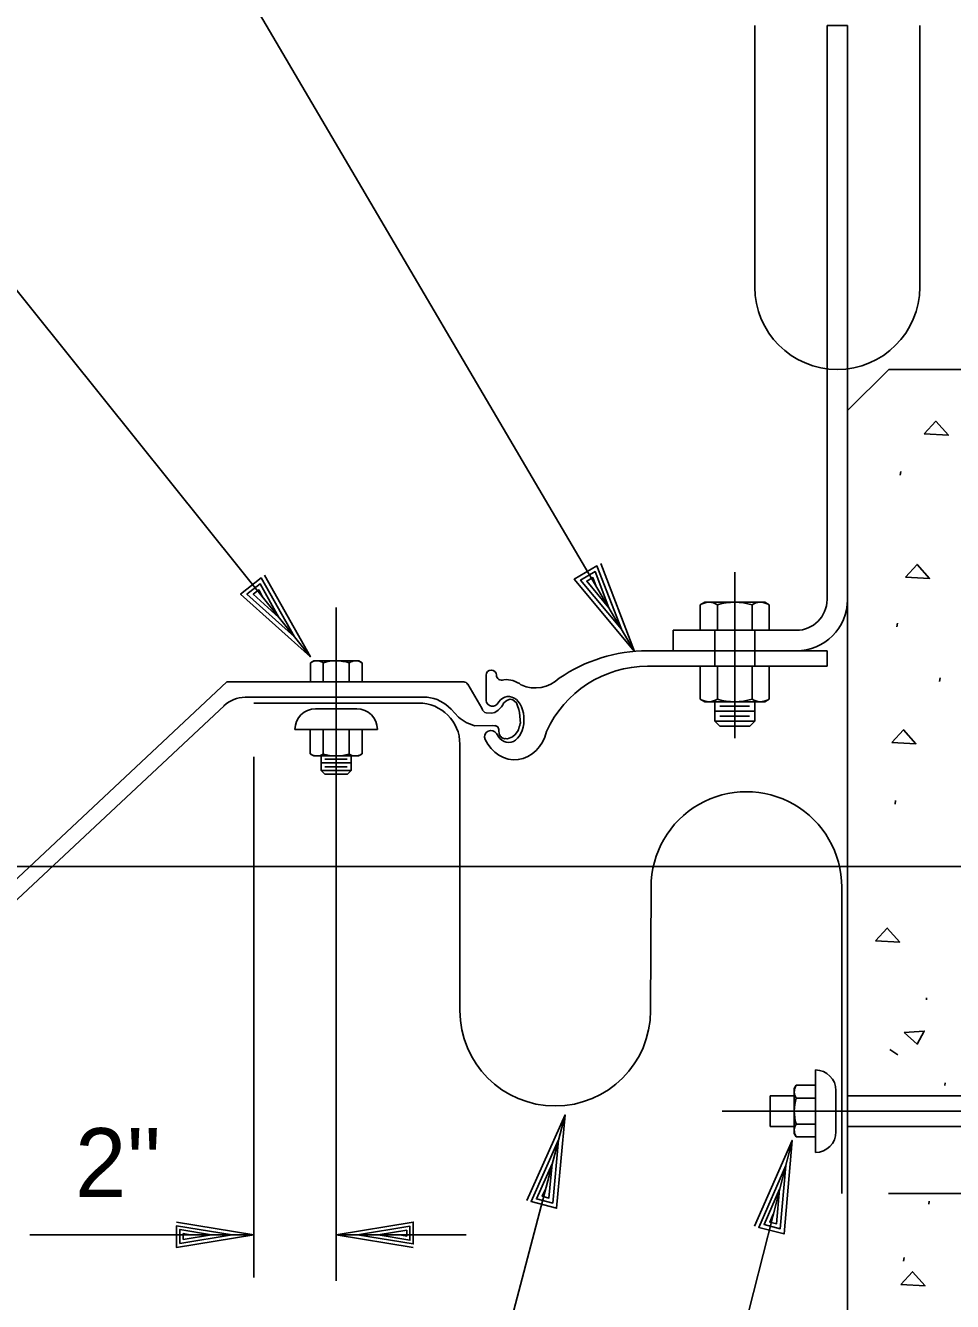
# Model space of a CAD drawing. Extents: x 22369.6 to 22428.3, y 22369.6 to 22415.
# Drawn here: x 22402.55 to 22405.041, y 22382.294 to 22385.725 of the extents above; entities that cross this region are included whole.
import ezdxf

# ---------------------------------------------------------------- set-up
doc = ezdxf.new("R2010")
doc.units = 0
for name, color, linetype in [('Level 1', 7, 'Continuous'), ('Level 10', 7, 'Continuous'), ('Level 2', 7, 'Continuous'), ('Level 3', 7, 'Continuous'), ('Level 4', 7, 'Continuous'), ('Level 7', 7, 'Continuous'), ('Level 8', 7, 'Continuous')]:
    doc.layers.add(name, color=color, linetype=linetype)

msp = doc.modelspace()

# ---------------------------------------------------------------- linework, layer by layer
at = {"layer": 'Level 1'}
for p, q in [((22404.1866, 22384.0421), (22402.6561, 22386.6455)), ((22402.4393, 22385.1206), (22403.3156, 22384.0274)), ((22404.456, 22384.2551), (22404.456, 22384.0022)), ((22403.3847, 22384.1599), (22403.3847, 22382.3487)), ((22404.3754, 22384.1741), (22404.3629, 22384.1669)), ((22404.3629, 22384.0987), (22404.3629, 22384.1669)), ((22404.3754, 22384.1741), (22404.5365, 22384.1741)), ((22404.4094, 22384.167), (22404.4094, 22384.0987)), ((22404.5026, 22384.167), (22404.5026, 22384.0987)), ((22404.5365, 22384.1741), (22404.549, 22384.1669)), ((22404.549, 22384.0987), (22404.549, 22384.1669)), ((22403.2723, 22384.0814), (22403.2723, 22384.0814)), ((22404.1515, 22384.1019), (22404.1515, 22384.1019)), ((22404.4021, 22384.0022), (22404.4021, 22384.0987)), ((22404.5099, 22384.0022), (22404.5099, 22384.0987)), ((22403.3249, 22384.0167), (22403.3155, 22384.0112)), ((22403.3155, 22383.9602), (22403.3155, 22384.0112)), ((22403.3156, 22384.0274), (22403.3156, 22384.0274)), ((22403.3249, 22384.0167), (22403.4454, 22384.0167)), ((22403.3502, 22384.0114), (22403.3502, 22383.9602)), ((22403.42, 22384.0114), (22403.42, 22383.9602)), ((22403.4454, 22384.0167), (22403.4548, 22384.0112)), ((22403.4548, 22383.9602), (22403.4548, 22384.0112)), ((22404.1866, 22384.0421), (22404.1866, 22384.0421)), ((22404.3629, 22384.0022), (22404.3629, 22383.9139)), ((22404.4094, 22383.9137), (22404.4094, 22384.0022)), ((22404.456, 22384.0022), (22404.456, 22384.0022)), ((22404.456, 22384.0022), (22404.456, 22383.809)), ((22404.5026, 22383.9137), (22404.5026, 22384.0022)), ((22404.549, 22384.0022), (22404.549, 22383.9139)), ((22404.3754, 22383.9066), (22404.3629, 22383.9139)), ((22404.5365, 22383.9066), (22404.549, 22383.9139)), ((22403.3293, 22383.8876), (22403.4402, 22383.8876)), ((22404.3754, 22383.9066), (22404.5365, 22383.9066)), ((22404.4021, 22383.8546), (22404.4021, 22383.9066)), ((22404.4021, 22383.8815), (22404.5099, 22383.8815)), ((22404.4157, 22383.8949), (22404.4958, 22383.8949)), ((22404.5099, 22383.8546), (22404.5099, 22383.9066)), ((22404.4021, 22383.8546), (22404.5099, 22383.8546)), ((22404.4021, 22383.8546), (22404.4156, 22383.8411)), ((22404.4156, 22383.8411), (22404.4964, 22383.8411)), ((22404.4157, 22383.868), (22404.4958, 22383.868)), ((22404.5099, 22383.8546), (22404.4964, 22383.8411)), ((22403.2739, 22383.8322), (22403.4956, 22383.8322)), ((22403.3151, 22383.8322), (22403.3151, 22383.7661)), ((22403.3499, 22383.7659), (22403.3499, 22383.8322)), ((22403.4196, 22383.7659), (22403.4196, 22383.8322)), ((22403.4543, 22383.8322), (22403.4543, 22383.7661)), ((22403.1631, 22383.7582), (22403.1631, 22382.3577)), ((22403.3245, 22383.7607), (22403.3151, 22383.7661)), ((22403.3245, 22383.7607), (22403.445, 22383.7607)), ((22403.3444, 22383.7217), (22403.3444, 22383.7607)), ((22403.3444, 22383.7419), (22403.4251, 22383.7419)), ((22403.3546, 22383.7519), (22403.4146, 22383.7519)), ((22403.4251, 22383.7217), (22403.4251, 22383.7607)), ((22403.445, 22383.7607), (22403.4543, 22383.7661)), ((22403.3444, 22383.7217), (22403.4251, 22383.7217)), ((22403.3444, 22383.7217), (22403.3545, 22383.7116)), ((22403.3545, 22383.7116), (22403.415, 22383.7116)), ((22403.3546, 22383.7318), (22403.4146, 22383.7318)), ((22403.4251, 22383.7217), (22403.415, 22383.7116)), ((22404.8872, 22383.6312), (22404.8886, 22383.6407)), ((22398.3749, 22383.4637), (22405.4638, 22383.4637)), ((22404.6728, 22382.6945), (22404.6728, 22382.9162)), ((22404.6161, 22382.8469), (22404.5514, 22382.8469)), ((22404.5514, 22382.7638), (22404.5514, 22382.8469)), ((22404.6161, 22382.866), (22404.6215, 22382.8754)), ((22404.6161, 22382.7455), (22404.6161, 22382.866)), ((22404.6725, 22382.8754), (22404.6215, 22382.8754)), ((22404.7282, 22382.7499), (22404.7282, 22382.8608)), ((22405.2026, 22382.8469), (22404.7592, 22382.8469)), ((22404.6214, 22382.8406), (22404.6725, 22382.8406)), ((22404.0001, 22382.7954), (22403.3267, 22380.2256)), ((22404.0001, 22382.7954), (22404.0001, 22382.7954)), ((22407.3997, 22382.8054), (22404.4222, 22382.8054)), ((22404.6161, 22382.7638), (22404.5514, 22382.7638)), ((22404.6161, 22382.7455), (22404.6215, 22382.7361)), ((22404.6214, 22382.7709), (22404.6725, 22382.7709)), ((22405.2026, 22382.7638), (22404.7592, 22382.7638)), ((22403.9826, 22382.7285), (22403.9826, 22382.7285)), ((22404.6102, 22382.7267), (22404.2046, 22381.1322)), ((22404.6102, 22382.7267), (22404.6102, 22382.7267)), ((22404.6725, 22382.7361), (22404.6215, 22382.7361)), ((22404.5931, 22382.6597), (22404.5931, 22382.6597)), ((22406.7358, 22382.5837), (22404.8694, 22382.5837)), ((22403.1631, 22382.4729), (22402.561, 22382.4729)), ((22403.1054, 22382.4729), (22403.1054, 22382.4729)), ((22403.1631, 22382.4729), (22403.1631, 22382.4729)), ((22403.7343, 22382.4729), (22403.3847, 22382.4729)), ((22403.3847, 22382.4729), (22403.3847, 22382.4729)), ((22403.4424, 22382.4729), (22403.4424, 22382.4729))]:
    msp.add_line(p, q, dxfattribs=at)
for points in [[(22404.0959, 22384.278), (22404.1866, 22384.0421), (22404.0246, 22384.2361), (22404.0856, 22384.2719), (22404.1515, 22384.1019), (22404.0415, 22384.2336), (22404.0806, 22384.2566), (22404.1177, 22384.1593), (22404.0584, 22384.2312), (22404.0745, 22384.2407), (22404.0826, 22384.2191)], [(22403.1922, 22384.2473), (22403.3156, 22384.0274), (22403.1279, 22384.1957), (22403.1829, 22384.2398), (22403.2723, 22384.0814), (22403.1449, 22384.1957), (22403.1802, 22384.224), (22403.2307, 22384.1333), (22403.1619, 22384.1957), (22403.1765, 22384.2074), (22403.1875, 22384.1872)], [(22403.8972, 22382.5653), (22404.0001, 22382.7954), (22403.977, 22382.5444), (22403.9088, 22382.5623), (22403.9826, 22382.7285), (22403.9668, 22382.5581), (22403.9231, 22382.5695), (22403.9657, 22382.6642), (22403.9566, 22382.5717), (22403.9386, 22382.5764), (22403.9482, 22382.5973)], [(22404.5089, 22382.4959), (22404.6102, 22382.7267), (22404.5888, 22382.4755), (22404.5205, 22382.4929), (22404.5931, 22382.6597), (22404.5786, 22382.4891), (22404.5347, 22382.5003), (22404.5767, 22382.5953), (22404.5683, 22382.5027), (22404.5502, 22382.5073), (22404.5597, 22382.5282)], [(22402.9558, 22382.5072), (22403.1631, 22382.4729), (22402.9558, 22382.4385), (22402.9558, 22382.4972), (22403.1054, 22382.4729), (22402.9647, 22382.4496), (22402.9647, 22382.4873), (22403.05, 22382.4729), (22402.9735, 22382.4607), (22402.9735, 22382.4762), (22402.9924, 22382.4729)], [(22403.592, 22382.4385), (22403.3847, 22382.4729), (22403.592, 22382.5072), (22403.592, 22382.4485), (22403.4424, 22382.4729), (22403.5831, 22382.4961), (22403.5831, 22382.4584), (22403.4978, 22382.4729), (22403.5743, 22382.4851), (22403.5743, 22382.4695), (22403.5554, 22382.4729)]]:
    msp.add_lwpolyline(points, dxfattribs=at)
for centre, radius, start, end in [((22404.3865, 22384.1338), 0.0404, 55.489, 120.2876), ((22404.4554, 22384.0125), 0.1616, 73.0184, 106.4966), ((22404.5255, 22384.1338), 0.0404, 59.7124, 124.511), ((22403.3331, 22383.9865), 0.0302, 55.489, 120.2876), ((22403.3847, 22383.8957), 0.1209, 73.0184, 106.4966), ((22403.4371, 22383.9865), 0.0302, 59.7124, 124.511), ((22404.3865, 22383.947), 0.0404, 239.7124, 304.511), ((22404.4554, 22384.0682), 0.1616, 253.5034, 286.9816), ((22404.5255, 22383.947), 0.0404, 235.489, 300.2876), ((22403.3293, 22383.8322), 0.0554, 90, 180), ((22403.4402, 22383.8322), 0.0554, 0, 90), ((22403.3328, 22383.7909), 0.0302, 239.7124, 304.511), ((22403.3843, 22383.8816), 0.1209, 253.5034, 286.9816), ((22403.4367, 22383.7909), 0.0302, 235.489, 300.2876), ((22404.6728, 22382.8608), 0.0554, 0, 90), ((22404.6463, 22382.8577), 0.0302, 149.7124, 214.511), ((22404.737, 22382.8053), 0.1209, 163.0184, 196.4966), ((22404.6463, 22382.7538), 0.0302, 145.489, 210.2876), ((22404.6728, 22382.7499), 0.0554, 270, 0)]:
    msp.add_arc(centre, radius, start, end, dxfattribs=at)
at = {"layer": 'Level 10'}
for p, q in [((22404.51, 22385.022), (22404.51, 22385.7253)), ((22404.9533, 22385.022), (22404.9533, 22385.7253))]:
    msp.add_line(p, q, dxfattribs=at)
msp.add_arc((22404.7317, 22385.022), 0.2217, 180, 0, dxfattribs=at)
at = {"layer": 'Level 2'}
for p, q in [((22404.7041, 22384.1814), (22404.7041, 22385.7253)), ((22404.7592, 22385.7253), (22404.7041, 22385.7253)), ((22404.7592, 22384.1814), (22404.7592, 22385.7253)), ((22404.6214, 22384.0987), (22404.2905, 22384.0987)), ((22404.2905, 22384.0435), (22404.2905, 22384.0987)), ((22404.7041, 22384.0435), (22404.2216, 22384.0435)), ((22404.7041, 22384.0435), (22404.7041, 22384.0022)), ((22403.7879, 22383.9082), (22403.7879, 22383.9778)), ((22403.8155, 22383.9783), (22403.8155, 22383.9778)), ((22404.7041, 22384.0022), (22404.2216, 22384.0022)), ((22402.0993, 22383.0308), (22403.0913, 22383.96)), ((22403.0913, 22383.96), (22403.728, 22383.96)), ((22403.7382, 22383.9541), (22403.7763, 22383.8895)), ((22403.1403, 22383.9186), (22403.6291, 22383.9186)), ((22402.0922, 22382.9675), (22403.0842, 22383.8966)), ((22403.6934, 22383.8865), (22403.7134, 22383.865)), ((22403.7576, 22383.8422), (22403.8041, 22383.8424))]:
    msp.add_line(p, q, dxfattribs=at)
msp.add_lwpolyline([(22403.7763, 22383.8895), (22403.7781, 22383.8846), (22403.7776, 22383.8846), (22403.7845, 22383.8778), (22403.788, 22383.8768), (22403.8034, 22383.8763), (22403.811, 22383.8776), (22403.8203, 22383.8836), (22403.8295, 22383.8932), (22403.8325, 22383.8986), (22403.8338, 22383.8998), (22403.8347, 22383.9026), (22403.8408, 22383.9084), (22403.8452, 22383.9112), (22403.8524, 22383.9137), (22403.8595, 22383.9115), (22403.8694, 22383.9041), (22403.8724, 22383.8953), (22403.8757, 22383.8857), (22403.8777, 22383.8781), (22403.88, 22383.8483), (22403.8795, 22383.8487), (22403.8787, 22383.8429), (22403.877, 22383.8387), (22403.8747, 22383.8308), (22403.8719, 22383.8262), (22403.8663, 22383.8184), (22403.8586, 22383.8126), (22403.8545, 22383.8101), (22403.8452, 22383.807), (22403.8441, 22383.8073), (22403.8436, 22383.8066), (22403.8398, 22383.8073), (22403.8375, 22383.8071), (22403.831, 22383.8096), (22403.8289, 22383.8101), (22403.8289, 22383.8109), (22403.8256, 22383.8143), (22403.8231, 22383.8205), (22403.8224, 22383.8296), (22403.8223, 22383.8318), (22403.8191, 22383.8389), (22403.812, 22383.8426), (22403.8117, 22383.8417), (22403.8117, 22383.8422), (22403.8041, 22383.8424)], dxfattribs=at)
for centre, radius, start, end in [((22404.6214, 22384.1814), 0.0827, 270, 0), ((22404.6214, 22384.1814), 0.1378, 270, 0), ((22404.2216, 22383.6248), 0.4187, 90, 124.5362), ((22403.8017, 22383.9778), 0.0138, 0, 180), ((22403.8293, 22383.9783), 0.0138, 180.0038, 294.2261), ((22404.2216, 22383.7052), 0.297, 90, 155.9098), ((22403.7268, 22383.9462), 0.0138, 34.4776, 84.9264), ((22403.8419, 22383.9028), 0.0633, 50.4241, 96.2781), ((22403.9195, 22384.0366), 0.0928, 246.293, 314.0783), ((22403.1403, 22383.8359), 0.0827, 90, 134.0411), ((22403.6189, 22383.8175), 0.1017, 42.8324, 84.2307), ((22403.8048, 22383.9117), 0.0172, 168.5103, 315.7394), ((22403.1403, 22383.8359), 0.0827, 132.7844, 133.4737), ((22403.7875, 22383.954), 0.1157, 230.268, 255.0673), ((22403.8007, 22383.8123), 0.0171, 30.0864, 204.1441)]:
    msp.add_arc(centre, radius, start, end, dxfattribs=at)
for centre, major_axis, ratio, start_param, end_param in [((22403.8482, 22383.8588), (0, -0.062), 0.666679, 5.371054, 10.276478), ((22403.8641, 22383.854), (0, -0.1034), 0.866676, 5.202938, 7.584426)]:
    msp.add_ellipse(centre, major_axis=major_axis, ratio=ratio, start_param=start_param, end_param=end_param, dxfattribs=at)
at = {"layer": 'Level 3'}
for p, q in [((22403.1631, 22383.9031), (22403.6064, 22383.9031)), ((22403.7172, 22383.7923), (22403.7172, 22383.0758)), ((22404.2298, 22383.0758), (22404.2311, 22383.4083)), ((22404.7437, 22383.4083), (22404.7437, 22382.5837))]:
    msp.add_line(p, q, dxfattribs=at)
for centre, radius, start, end in [((22403.6064, 22383.7923), 0.1108, 0, 90), ((22404.4874, 22383.4083), 0.2563, 359.9969, 180), ((22403.9735, 22383.0758), 0.2563, 180, 0)]:
    msp.add_arc(centre, radius, start, end, dxfattribs=at)
at = {"layer": 'Level 7'}
for p, q in [((22404.8701, 22384.8004), (22404.7592, 22384.6895)), ((22406.2001, 22384.8004), (22404.8701, 22384.8004)), ((22404.7592, 22382.2512), (22404.7592, 22384.6895))]:
    msp.add_line(p, q, dxfattribs=at)
at = {"layer": 'Level 8'}
for p, q in [((22404.9009, 22384.516), (22404.9024, 22384.5256)), ((22404.8917, 22384.108), (22404.8932, 22384.1176)), ((22405.0064, 22383.9613), (22405.0078, 22383.9709)), ((22404.9715, 22383.1046), (22404.9715, 22383.1104)), ((22405.0206, 22382.8741), (22405.0213, 22382.8814)), ((22404.9776, 22382.5555), (22404.9789, 22382.563)), ((22404.9101, 22382.4024), (22404.9116, 22382.412))]:
    msp.add_line(p, q, dxfattribs=at)
for points in [[(22404.965, 22384.627), (22404.9965, 22384.6611), (22405.0302, 22384.6234)], [(22404.9146, 22384.2419), (22404.9461, 22384.276), (22404.9798, 22384.2383)], [(22404.8779, 22383.7972), (22404.9094, 22383.8313), (22404.9431, 22383.7936)], [(22404.8346, 22383.2637), (22404.866, 22383.2978), (22404.8997, 22383.2601)], [(22404.9112, 22383.0172), (22404.9464, 22382.9858), (22404.9653, 22383.021)], [(22404.9025, 22382.3396), (22404.9339, 22382.3737), (22404.9677, 22382.336)]]:
    msp.add_lwpolyline(points, close=True, dxfattribs=at)
msp.add_lwpolyline([(22404.894, 22382.957), (22404.8733, 22382.9709)], dxfattribs=at)

# ---------------------------------------------------------------- texts
at = {"layer": 'Level 4'}
msp.add_text("2''", height=0.1853, dxfattribs=at).set_placement((22402.6829, 22382.5745))

doc.saveas('drawing.dxf')
